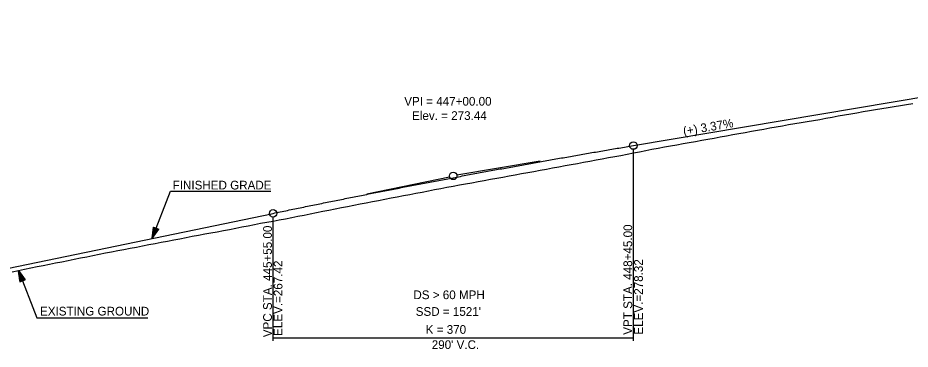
# Model space of a CAD drawing. Extents: x 69 to 2003113, y 512 to 837401.
# Drawn here: x 1922713 to 1923431, y 831232 to 831499 of the extents above; entities that cross this region are included whole.
import ezdxf

# ---------------------------------------------------------------- set-up
doc = ezdxf.new("R2010")
doc.units = 0
for name, color, linetype in [('BR_CENTER LINE BASELINE', 7, 'Continuous'), ('BR_CONCRETE', 7, 'Continuous'), ('BR_GRID DOTS', 7, 'Continuous'), ('BR_GRID LINES', 7, 'Continuous'), ('BR_TEXT', 7, 'Continuous'), ('RD_PD_ALT1_TrvlWay', 7, 'Continuous'), ('RD_SHT_IplotShp', 7, 'Continuous')]:
    doc.layers.add(name, color=color, linetype=linetype)

msp = doc.modelspace()

# ---------------------------------------------------------------- linework, layer by layer
at = {"layer": 'BR_CENTER LINE BASELINE'}
for p, q in [((1923133.14, 831383.28), (1923066.08, 831371.99)), ((1922993.6, 831357.07), (1923060.19, 831370.89))]:
    msp.add_line(p, q, dxfattribs=at)
msp.add_circle((1923063.12, 831371.5), 3, dxfattribs=at)
at = {"layer": 'BR_GRID DOTS'}
for p, q in [((1923208.12, 831238.9), (1923208.12, 831392.9)), ((1922918.12, 831238.9), (1922918.12, 831338.4)), ((1922918.12, 831241.4), (1923208.12, 831241.4))]:
    msp.add_line(p, q, dxfattribs=at)
for centre in [(1923208.12, 831395.9), (1922918.12, 831341.4)]:
    msp.add_circle(centre, 3, dxfattribs=at)
at = {"layer": 'BR_GRID LINES'}
for p, q in [((1923208.12, 831395.9), (1923818.12, 831498.59)), ((1922653.12, 831286.4), (1922918.12, 831341.4))]:
    msp.add_line(p, q, dxfattribs=at)
msp.add_spline([(1922918.12, 831341.4), (1922923.92, 831342.6), (1922929.72, 831343.8), (1922935.52, 831344.99), (1922941.32, 831346.18), (1922947.12, 831347.36), (1922952.92, 831348.54), (1922958.72, 831349.72), (1922964.52, 831350.89), (1922970.32, 831352.05), (1922976.12, 831353.21), (1922981.92, 831354.37), (1922987.72, 831355.52), (1922993.52, 831356.67), (1922999.32, 831357.81), (1923005.12, 831358.95), (1923010.92, 831360.08), (1923016.72, 831361.21), (1923022.52, 831362.33), (1923028.32, 831363.45), (1923034.12, 831364.57), (1923039.92, 831365.68), (1923045.72, 831366.78), (1923051.52, 831367.89), (1923057.32, 831368.98), (1923063.12, 831370.07), (1923068.92, 831371.16), (1923074.72, 831372.25), (1923080.52, 831373.32), (1923086.32, 831374.4), (1923092.12, 831375.47), (1923097.92, 831376.53), (1923103.72, 831377.59), (1923109.52, 831378.65), (1923115.32, 831379.7), (1923121.12, 831380.75), (1923126.92, 831381.79), (1923132.72, 831382.83), (1923138.52, 831383.86), (1923144.32, 831384.89), (1923150.12, 831385.91), (1923155.92, 831386.93), (1923161.72, 831387.95), (1923167.52, 831388.96), (1923173.32, 831389.96), (1923179.12, 831390.97), (1923184.92, 831391.96), (1923190.72, 831392.95), (1923196.52, 831393.94), (1923202.32, 831394.93), (1923208.12, 831395.9)], degree=3, dxfattribs=at)
at = {"layer": 'BR_TEXT'}
for points in [[(1923363.08, 831417.91), (1923368.08, 831418.84), (1923373.08, 831419.75), (1923378.08, 831420.63), (1923383.08, 831421.48), (1923388.08, 831422.33), (1923393.08, 831423.19), (1923398.08, 831424.04), (1923403.08, 831424.87), (1923408.08, 831425.67), (1923413.08, 831426.51), (1923418.08, 831427.33), (1923423.08, 831428.17), (1923428.08, 831429.02), (1923433.08, 831429.85)], [(1922863.08, 831324.8), (1922868.08, 831325.71), (1922873.08, 831326.63), (1922878.08, 831327.59), (1922883.08, 831328.52), (1922888.08, 831329.48), (1922893.08, 831330.48), (1922898.08, 831331.48), (1922903.08, 831332.45), (1922908.08, 831333.38), (1922913.08, 831334.28), (1922918.08, 831335.21), (1922923.08, 831336.15), (1922928.08, 831337.09), (1922933.08, 831338.04), (1922938.08, 831339.02), (1922943.08, 831340.02), (1922948.08, 831341.02), (1922953.08, 831342.02), (1922958.08, 831343.02), (1922963.08, 831344), (1922968.08, 831344.99), (1922973.08, 831346), (1922978.08, 831347.01), (1922983.08, 831348.02), (1922988.08, 831348.98), (1922993.08, 831349.94), (1922998.08, 831350.9), (1923003.08, 831351.83), (1923008.08, 831352.8), (1923013.08, 831353.77), (1923018.08, 831354.71), (1923023.08, 831355.69), (1923028.08, 831356.64), (1923033.08, 831357.58), (1923038.08, 831358.53), (1923043.08, 831359.49), (1923048.08, 831360.45), (1923053.08, 831361.4), (1923058.08, 831362.34), (1923063.08, 831363.28), (1923068.08, 831364.21), (1923073.08, 831365.13), (1923078.08, 831366.04), (1923083.08, 831366.97), (1923088.08, 831367.87), (1923093.08, 831368.77), (1923098.08, 831369.68), (1923103.08, 831370.57), (1923108.08, 831371.47), (1923113.08, 831372.38), (1923118.08, 831373.33), (1923123.08, 831374.2), (1923128.08, 831375.1), (1923133.08, 831376.01), (1923138.08, 831376.91), (1923143.08, 831377.88), (1923148.08, 831378.83), (1923153.08, 831379.76), (1923158.08, 831380.68), (1923163.08, 831381.57), (1923168.08, 831382.46), (1923173.08, 831383.38), (1923178.08, 831384.35), (1923183.08, 831385.28), (1923188.08, 831386.21), (1923193.08, 831387.12), (1923198.08, 831388.02), (1923203.08, 831388.98), (1923208.08, 831389.93), (1923213.08, 831390.91), (1923218.08, 831391.93), (1923223.08, 831392.92), (1923228.08, 831393.85), (1923233.08, 831394.75), (1923238.08, 831395.66), (1923243.08, 831396.54), (1923248.08, 831397.43), (1923253.08, 831398.33), (1923258.08, 831399.2), (1923263.08, 831400.14), (1923268.08, 831401.06), (1923273.08, 831401.97), (1923278.08, 831402.9), (1923283.08, 831403.8), (1923288.08, 831404.7), (1923293.08, 831405.61), (1923298.08, 831406.53), (1923303.08, 831407.43), (1923308.08, 831408.33), (1923313.08, 831409.22), (1923318.08, 831410.09), (1923323.08, 831410.96), (1923328.08, 831411.86), (1923333.08, 831412.75), (1923338.08, 831413.64), (1923343.08, 831414.56), (1923348.08, 831415.36), (1923353.08, 831416.15), (1923358.08, 831416.99), (1923363.08, 831417.91)], [(1922708.08, 831294.47), (1922713.08, 831295.46), (1922718.08, 831296.53), (1922723.08, 831297.55), (1922728.08, 831298.54), (1922733.08, 831299.54), (1922738.08, 831300.53), (1922743.08, 831301.52), (1922748.08, 831302.49), (1922753.08, 831303.51), (1922758.08, 831304.53), (1922763.08, 831305.58), (1922768.08, 831306.55), (1922773.08, 831307.52), (1922778.08, 831308.5), (1922783.08, 831309.52), (1922788.08, 831310.49), (1922793.08, 831311.41), (1922798.08, 831312.33), (1922803.08, 831313.35), (1922808.08, 831314.32), (1922813.08, 831315.3), (1922818.08, 831316.27), (1922823.08, 831317.24), (1922828.08, 831318.17), (1922833.08, 831319.13), (1922838.08, 831320.08), (1922843.08, 831321.01), (1922848.08, 831321.97), (1922853.08, 831322.93), (1922858.08, 831323.87), (1922863.08, 831324.8)]]:
    msp.add_lwpolyline(points, dxfattribs=at)
at = {"layer": 'RD_PD_ALT1_TrvlWay'}
for p, q in [((1922820.67, 831321.17), (1922835.63, 831359.13)), ((1922835.63, 831359.13), (1922916.41, 831359.13)), ((1922820.67, 831321.17), (1922821.87, 831330.37)), ((1922820.67, 831321.17), (1922821.87, 831330.37)), ((1922823.97, 831329.55), (1922820.67, 831321.17)), ((1922823.97, 831329.55), (1922820.67, 831321.17)), ((1922820.67, 831321.17), (1922826.06, 831328.72)), ((1922820.67, 831321.17), (1922826.06, 831328.72)), ((1922821.87, 831330.37), (1922826.06, 831328.72)), ((1922821.87, 831330.37), (1922826.06, 831328.72)), ((1922713.08, 831295.46), (1922728.04, 831257.51)), ((1922716.38, 831287.09), (1922713.08, 831295.46)), ((1922713.08, 831295.46), (1922718.48, 831287.92)), ((1922713.08, 831295.46), (1922714.29, 831286.27)), ((1922714.29, 831286.27), (1922718.48, 831287.92)), ((1922728.04, 831257.51), (1922817.23, 831257.51))]:
    msp.add_line(p, q, dxfattribs=at)
for points in [[(1922823.87, 831329.47), (1922820.79, 831321.67), (1922823.83, 831329.54), (1922820.87, 831322.06), (1922823.73, 831329.54), (1922820.89, 831322.33), (1922823.62, 831329.56), (1922820.92, 831322.66), (1922823.54, 831329.61), (1922821, 831323.15), (1922823.43, 831329.68), (1922821.08, 831323.68), (1922823.31, 831329.68), (1922821.14, 831324.08), (1922823.23, 831329.74), (1922821.2, 831324.53), (1922823.12, 831329.72), (1922821.26, 831324.93), (1922823.07, 831329.82), (1922821.29, 831325.28), (1922822.93, 831329.83), (1922821.35, 831325.77), (1922822.83, 831329.89), (1922821.46, 831326.37), (1922822.74, 831329.95), (1922821.47, 831326.79), (1922822.63, 831329.99), (1922821.56, 831327.41), (1922822.51, 831330), (1922821.65, 831327.92), (1922822.41, 831330.1), (1922821.71, 831328.36), (1922822.31, 831330.1), (1922821.75, 831328.76), (1922822.23, 831330.19), (1922821.82, 831329.25), (1922822.12, 831330.16), (1922821.9, 831329.8), (1922822, 831330.16)], [(1922823.87, 831329.47), (1922820.79, 831321.67), (1922823.83, 831329.54), (1922820.87, 831322.06), (1922823.73, 831329.54), (1922820.89, 831322.33), (1922823.62, 831329.56), (1922820.92, 831322.66), (1922823.54, 831329.61), (1922821, 831323.15), (1922823.43, 831329.68), (1922821.08, 831323.68), (1922823.31, 831329.68), (1922821.14, 831324.08), (1922823.23, 831329.74), (1922821.2, 831324.53), (1922823.12, 831329.72), (1922821.26, 831324.93), (1922823.07, 831329.82), (1922821.29, 831325.28), (1922822.93, 831329.83), (1922821.35, 831325.77), (1922822.83, 831329.89), (1922821.46, 831326.37), (1922822.74, 831329.95), (1922821.47, 831326.79), (1922822.63, 831329.99), (1922821.56, 831327.41), (1922822.51, 831330), (1922821.65, 831327.92), (1922822.41, 831330.1), (1922821.71, 831328.36), (1922822.31, 831330.1), (1922821.75, 831328.76), (1922822.23, 831330.19), (1922821.82, 831329.25), (1922822.12, 831330.16), (1922821.9, 831329.8), (1922822, 831330.16)], [(1922820.94, 831321.69), (1922823.99, 831329.42), (1922821.1, 831321.95), (1922824.09, 831329.38), (1922821.26, 831322.19), (1922824.17, 831329.38), (1922821.44, 831322.4), (1922824.24, 831329.34), (1922821.64, 831322.66), (1922824.33, 831329.32), (1922821.82, 831322.91), (1922824.4, 831329.3), (1922822.04, 831323.2), (1922824.49, 831329.28), (1922822.28, 831323.57), (1922824.61, 831329.21), (1922822.49, 831323.88), (1922824.69, 831329.22), (1922822.72, 831324.21), (1922824.77, 831329.17), (1922822.96, 831324.52), (1922824.86, 831329.13), (1922823.19, 831324.87), (1922824.91, 831329.06), (1922823.51, 831325.32), (1922825.01, 831329.06), (1922823.75, 831325.61), (1922825.09, 831329.06), (1922824.04, 831325.99), (1922825.16, 831328.99), (1922824.28, 831326.4), (1922825.26, 831328.94), (1922824.5, 831326.71), (1922825.34, 831328.84), (1922824.75, 831326.99), (1922825.41, 831328.82), (1922825.04, 831327.46), (1922825.56, 831328.84), (1922825.22, 831327.73), (1922825.7, 831328.78), (1922825.41, 831327.9), (1922825.8, 831328.64), (1922825.92, 831328.69), (1922825.77, 831328.66)], [(1922820.94, 831321.69), (1922823.99, 831329.42), (1922821.1, 831321.95), (1922824.09, 831329.38), (1922821.26, 831322.19), (1922824.17, 831329.38), (1922821.44, 831322.4), (1922824.24, 831329.34), (1922821.64, 831322.66), (1922824.33, 831329.32), (1922821.82, 831322.91), (1922824.4, 831329.3), (1922822.04, 831323.2), (1922824.49, 831329.28), (1922822.28, 831323.57), (1922824.61, 831329.21), (1922822.49, 831323.88), (1922824.69, 831329.22), (1922822.72, 831324.21), (1922824.77, 831329.17), (1922822.96, 831324.52), (1922824.86, 831329.13), (1922823.19, 831324.87), (1922824.91, 831329.06), (1922823.51, 831325.32), (1922825.01, 831329.06), (1922823.75, 831325.61), (1922825.09, 831329.06), (1922824.04, 831325.99), (1922825.16, 831328.99), (1922824.28, 831326.4), (1922825.26, 831328.94), (1922824.5, 831326.71), (1922825.34, 831328.84), (1922824.75, 831326.99), (1922825.41, 831328.82), (1922825.04, 831327.46), (1922825.56, 831328.84), (1922825.22, 831327.73), (1922825.7, 831328.78), (1922825.41, 831327.9), (1922825.8, 831328.64), (1922825.92, 831328.69), (1922825.77, 831328.66)], [(1922716.28, 831287.17), (1922713.21, 831294.97), (1922716.25, 831287.1), (1922713.28, 831294.57), (1922716.15, 831287.1), (1922713.31, 831294.3), (1922716.04, 831287.07), (1922713.34, 831293.98), (1922715.96, 831287.02), (1922713.41, 831293.48), (1922715.84, 831286.96), (1922713.5, 831292.96), (1922715.73, 831286.95), (1922713.55, 831292.56), (1922715.65, 831286.9), (1922713.61, 831292.1), (1922715.54, 831286.92), (1922713.67, 831291.71), (1922715.48, 831286.81), (1922713.71, 831291.36), (1922715.34, 831286.8), (1922713.76, 831290.86), (1922715.25, 831286.74), (1922713.88, 831290.27), (1922715.15, 831286.69), (1922713.88, 831289.85), (1922715.05, 831286.64), (1922713.97, 831289.22), (1922714.93, 831286.64), (1922714.07, 831288.72), (1922714.83, 831286.54), (1922714.12, 831288.28), (1922714.73, 831286.54), (1922714.16, 831287.88), (1922714.64, 831286.45), (1922714.23, 831287.38), (1922714.53, 831286.48), (1922714.31, 831286.83), (1922714.41, 831286.47)], [(1922713.36, 831294.94), (1922716.4, 831287.22), (1922713.52, 831294.69), (1922716.51, 831287.26), (1922713.67, 831294.45), (1922716.59, 831287.25), (1922713.85, 831294.24), (1922716.65, 831287.3), (1922714.06, 831293.98), (1922716.74, 831287.31), (1922714.23, 831293.73), (1922716.81, 831287.34), (1922714.45, 831293.43), (1922716.91, 831287.36), (1922714.69, 831293.07), (1922717.02, 831287.42), (1922714.9, 831292.75), (1922717.1, 831287.42), (1922715.13, 831292.42), (1922717.18, 831287.47), (1922715.37, 831292.12), (1922717.27, 831287.5), (1922715.61, 831291.77), (1922717.32, 831287.58), (1922715.93, 831291.31), (1922717.42, 831287.58), (1922716.16, 831291.03), (1922717.5, 831287.57), (1922716.45, 831290.64), (1922717.58, 831287.64), (1922716.69, 831290.24), (1922717.67, 831287.7), (1922716.92, 831289.92), (1922717.76, 831287.79), (1922717.17, 831289.64), (1922717.83, 831287.82), (1922717.45, 831289.17), (1922717.97, 831287.8), (1922717.64, 831288.91), (1922718.11, 831287.85), (1922717.82, 831288.74), (1922718.22, 831287.99), (1922718.34, 831287.94), (1922718.18, 831287.98)]]:
    msp.add_lwpolyline(points, dxfattribs=at)

# ---------------------------------------------------------------- texts
at = {"layer": 'BR_CENTER LINE BASELINE'}
msp.add_text('(+) 3.37%', height=7, rotation=9.55528, dxfattribs=at).set_placement((1923248.73, 831403.99))
at = {"layer": 'BR_CONCRETE'}
for s, p in [('VPT STA. 448+45.00 ', (1923207.12, 831243.77)), ('VPC STA. 445+55.00 ', (1922917.12, 831241.78)), ('ELEV.=278.32', (1923215.73, 831243.91)), ('ELEV.=267.42', (1922925.62, 831242.8))]:
    msp.add_text(s, height=7, rotation=90, dxfattribs=at).set_placement(p)
at = {"layer": 'BR_GRID DOTS'}
for s, p in [('DS > 60 MPH', (1923031.03, 831272.39)), ("SSD = 1521'", (1923032.9, 831258.98)), ('K = 370', (1923040.95, 831244.53)), ("290' V.C.", (1923045.81, 831232.31))]:
    msp.add_text(s, height=7, dxfattribs=at).set_placement(p)
at = {"layer": 'RD_PD_ALT1_TrvlWay'}
for s, p in [('FINISHED GRADE', (1922837.27, 831360.6)), ('EXISTING GROUND', (1922730.51, 831259.24))]:
    msp.add_text(s, height=7, dxfattribs=at).set_placement(p)
at = {"layer": 'RD_SHT_IplotShp'}
for s, p in [('VPI = 447+00.00', (1923023.7, 831428)), ('Elev. = 273.44', (1923030, 831416.5))]:
    msp.add_text(s, height=7, dxfattribs=at).set_placement(p)

doc.saveas('drawing.dxf')
